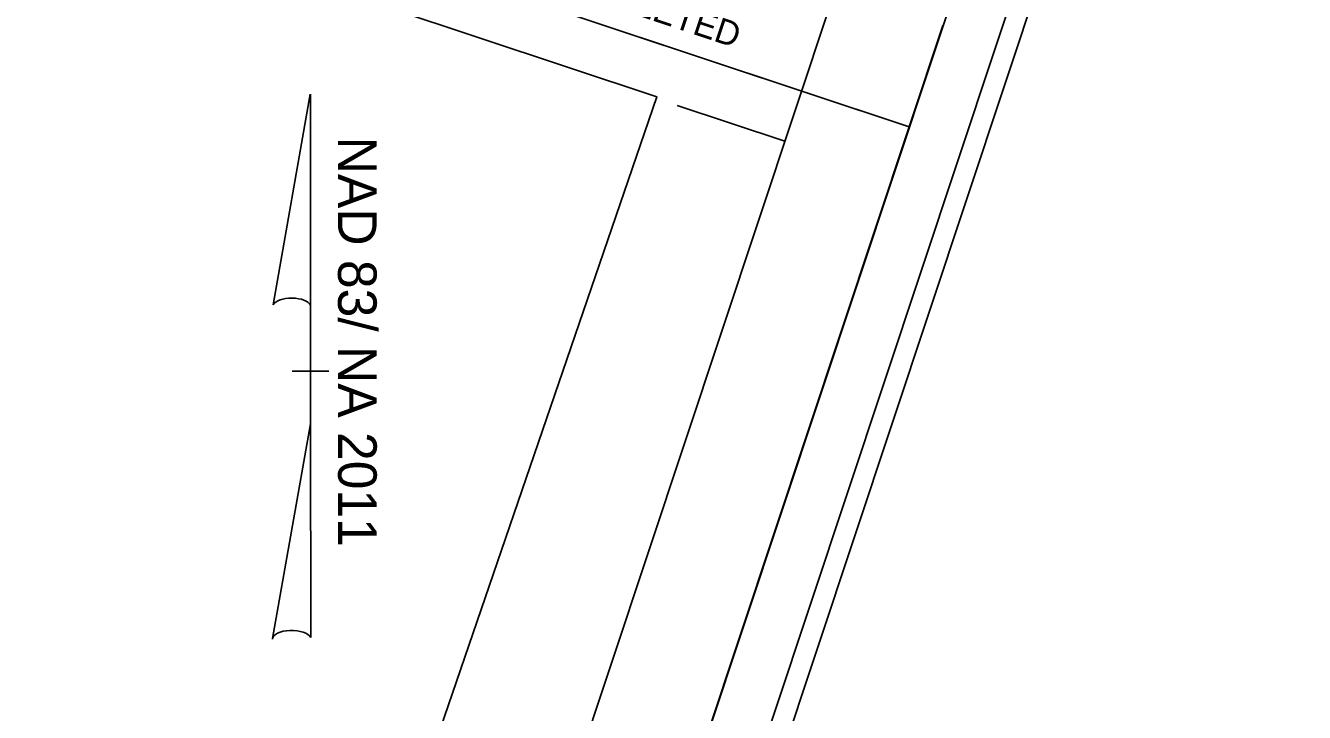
# Model space of a CAD drawing. Extents: x 2296288 to 2297455, y 600637 to 601606.
# Drawn here: x 2297286 to 2297455, y 601084.9 to 601175.7 of the extents above; entities that cross this region are included whole.
import ezdxf

# ---------------------------------------------------------------- set-up
doc = ezdxf.new("R2010")
doc.units = 0
for name, color, linetype in [('Exist DTM Drainline Cogo Comment', 7, 'Continuous'), ('Exist DTM Drainline Cogo Point CELL', 7, 'Continuous'), ('Exist Property Iron Pin CELL', 7, 'Continuous'), ('Exist Property Iron Pin Cogo Elevation', 7, 'Continuous'), ('Exist Property Iron Pin Cogo Number', 7, 'Continuous'), ('Exist Roads Curbs Cogo Comment', 7, 'Continuous'), ('Exist Roads Curbs Cogo Elevation', 7, 'Continuous'), ('Exist Roads Curbs Cogo Number', 7, 'Continuous'), ('Exist Roads Curbs Cogo Point CELL', 7, 'Continuous')]:
    doc.layers.add(name, color=color, linetype=linetype)

msp = doc.modelspace()

# ---------------------------------------------------------------- linework, layer by layer
at = {"layer": 'Exist DTM Drainline Cogo Comment'}
msp.add_lwpolyline([(2297440.6, 601276.06), (2296586.57, 601560.02), (2296387.8, 600962.2), (2297241.83, 600678.24)], close=True, dxfattribs=at)
at = {"layer": 'Exist DTM Drainline Cogo Point CELL'}
msp.add_lwpolyline([(2297421.64, 601266.56), (2296596.08, 601541.06), (2296406.77, 600971.7), (2297232.33, 600697.21)], close=True, dxfattribs=at)
at = {"layer": 'Exist Property Iron Pin CELL'}
for p, q in [((2297318.68, 601138.79), (2297323.6, 601166.6)), ((2297323.63, 601166.6), (2297323.63, 601137.92)), ((2297323.63, 601123.04), (2297323.63, 601138.76)), ((2297323.63, 601137.92), (2297323.63, 601138.73)), ((2297321.23, 601130), (2297321.2, 601130)), ((2297323.36, 601130), (2297321.23, 601130)), ((2297321.26, 601130), (2297326.06, 601130)), ((2297323.63, 601123.04), (2297318.62, 601094.69)), ((2297323.66, 601094.81), (2297323.63, 601123.04))]:
    msp.add_line(p, q, dxfattribs=at)
for centre, start_param, end_param in [((2297321.16, 601138.5), 0.216388, 2.908219), ((2297321.16, 601094.59), 0.201328, 3.141593)]:
    msp.add_ellipse(centre, major_axis=(2.54, -0.02), ratio=0.461098, start_param=start_param, end_param=end_param, dxfattribs=at)
at = {"layer": 'Exist Property Iron Pin Cogo Elevation'}
msp.add_line((2297386.35, 601160.39), (2297372.12, 601165.13), dxfattribs=at)
at = {"layer": 'Exist Property Iron Pin Cogo Number'}
msp.add_lwpolyline([(2296425.75, 600981.21), (2297152.11, 600739.71), (2297168.67, 600769.15), (2297226.75, 600750.14), (2297369.4, 601166.29), (2297286.75, 601193.77), (2297317.24, 601285.47), (2296605.59, 601522.09)], close=True, dxfattribs=at)
at = {"layer": 'Exist Roads Curbs Cogo Comment'}
for p, q in [((2297402.77, 601162.31), (2297288.88, 601200.18)), ((2297407.22, 601175.68), (2297402.77, 601162.3))]:
    msp.add_line(p, q, dxfattribs=at)
at = {"layer": 'Exist Roads Curbs Cogo Elevation'}
msp.add_lwpolyline([(2296586.57, 601560.02), (2296387.82, 600962.21), (2297241.85, 600678.25), (2297402.77, 601162.3), (2297288.88, 601200.18), (2297326.7, 601313.93)], close=True, dxfattribs=at)
at = {"layer": 'Exist Roads Curbs Cogo Number'}
msp.add_lwpolyline([(2297455.02, 601287.08), (2296496.23, 601605.87), (2296287.99, 600979.58), (2297246.78, 600660.79)], close=True, dxfattribs=at)
at = {"layer": 'Exist Roads Curbs Cogo Point CELL'}
msp.add_lwpolyline([(2297448.2, 601275.15), (2296499.38, 601590.63), (2296299.64, 600989.9), (2297248.47, 600674.42)], close=True, dxfattribs=at)

# ---------------------------------------------------------------- texts
at = {"layer": 'Exist Property Iron Pin CELL'}
msp.add_text('NAD 83/ NA 2011', height=5.1, rotation=270.0239, dxfattribs=at).set_placement((2297327.26, 601161.01))
at = {"layer": 'Exist Roads Curbs Cogo Comment'}
msp.add_text('UNLESS ALL SIGNATURES COMPLETED', height=3.3, rotation=341.6082, dxfattribs=at).set_placement((2297298.82, 601199.63))

doc.saveas('drawing.dxf')
